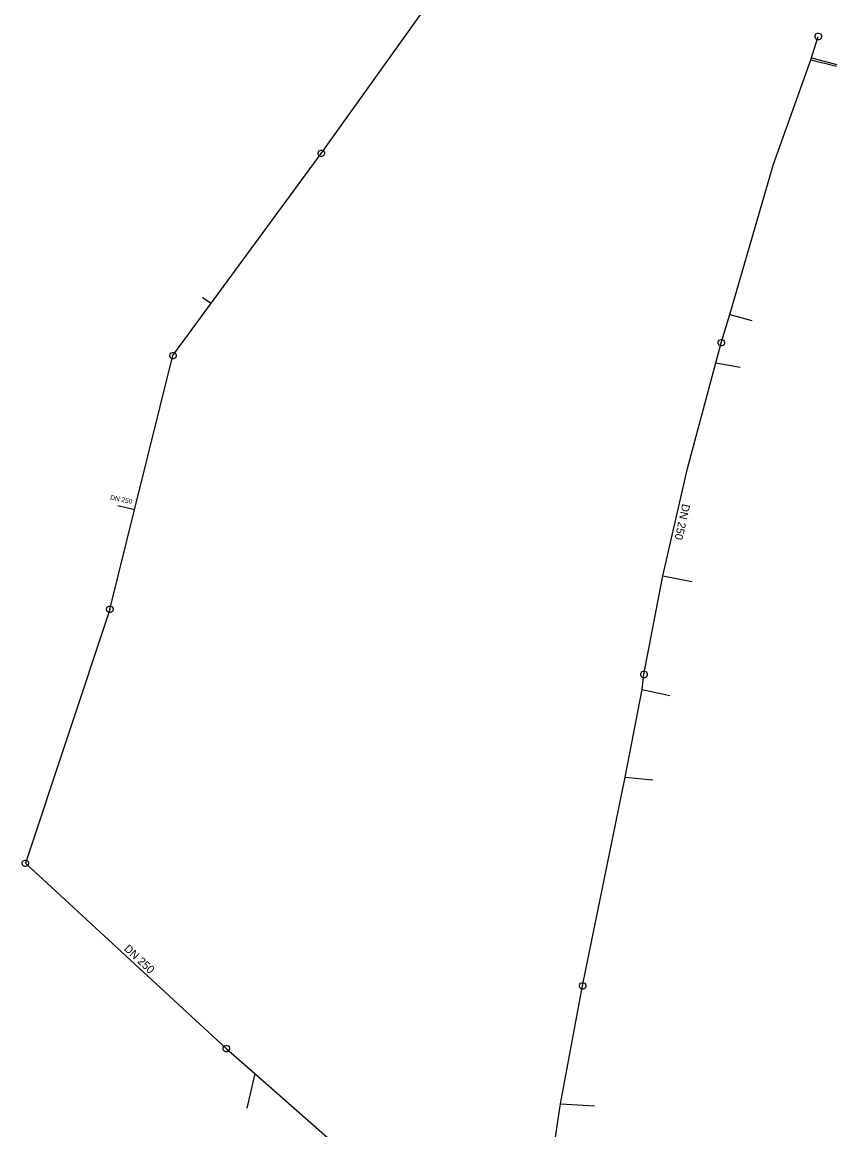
# Model space of a CAD drawing. Extents: x -717256 to -716843, y -1145423 to -1142840.
# Drawn here: x -717229.7 to -717102.4, y -1144225.5 to -1144052.4 of the extents above; entities that cross this region are included whole.
import ezdxf

# ---------------------------------------------------------------- set-up
doc = ezdxf.new("R2010")
doc.units = 0
doc.layers.add('Vrstva 30', color=7, linetype='Continuous')
doc.layers.add('Vrstva 31', color=7, linetype='Continuous')

msp = doc.modelspace()

# ---------------------------------------------------------------- linework, layer by layer
at = {"layer": 'Vrstva 30'}
for p, q in [((-717182.99, -1144072.917), (-717155.294, -1144034.126)), ((-717106.494, -1144058.295), (-717105.338, -1144054.658)), ((-717105.838, -1144054.558), (-717105.788, -1144054.408)), ((-717105.838, -1144054.758), (-717105.838, -1144054.558)), ((-717105.738, -1144055.008), (-717105.838, -1144054.758)), ((-717105.788, -1144054.408), (-717105.688, -1144054.258)), ((-717105.588, -1144055.108), (-717105.738, -1144055.008)), ((-717105.688, -1144054.258), (-717105.438, -1144054.158)), ((-717105.438, -1144055.158), (-717105.588, -1144055.108)), ((-717105.438, -1144054.158), (-717105.238, -1144054.158)), ((-717105.238, -1144055.158), (-717105.438, -1144055.158)), ((-717105.238, -1144054.158), (-717104.988, -1144054.258)), ((-717105.088, -1144055.108), (-717105.238, -1144055.158)), ((-717104.938, -1144055.008), (-717105.088, -1144055.108)), ((-717104.988, -1144054.258), (-717104.888, -1144054.408)), ((-717104.838, -1144054.758), (-717104.938, -1144055.008)), ((-717104.888, -1144054.408), (-717104.838, -1144054.558)), ((-717104.838, -1144054.558), (-717104.838, -1144054.758)), ((-717112.339, -1144074.608), (-717106.494, -1144058.295)), ((-717183.49, -1144072.817), (-717183.44, -1144072.667)), ((-717183.49, -1144073.017), (-717183.49, -1144072.817)), ((-717183.44, -1144072.667), (-717183.34, -1144072.517)), ((-717183.34, -1144072.517), (-717183.09, -1144072.417)), ((-717183.09, -1144072.417), (-717182.89, -1144072.417)), ((-717182.89, -1144072.417), (-717182.64, -1144072.517)), ((-717182.64, -1144072.517), (-717182.54, -1144072.667)), ((-717182.54, -1144072.667), (-717182.49, -1144072.817)), ((-717182.49, -1144072.817), (-717182.49, -1144073.017)), ((-717206.171, -1144104.518), (-717182.99, -1144072.917)), ((-717183.39, -1144073.267), (-717183.49, -1144073.017)), ((-717183.24, -1144073.367), (-717183.39, -1144073.267)), ((-717183.09, -1144073.417), (-717183.24, -1144073.367)), ((-717182.89, -1144073.417), (-717183.09, -1144073.417)), ((-717182.74, -1144073.367), (-717182.89, -1144073.417)), ((-717182.59, -1144073.267), (-717182.74, -1144073.367)), ((-717182.49, -1144073.017), (-717182.59, -1144073.267)), ((-717119.132, -1144098.105), (-717112.339, -1144074.608)), ((-717120.483, -1144102.511), (-717119.132, -1144098.105)), ((-717120.983, -1144102.411), (-717120.933, -1144102.261)), ((-717120.933, -1144102.261), (-717120.833, -1144102.111)), ((-717120.833, -1144102.111), (-717120.583, -1144102.011)), ((-717120.583, -1144102.011), (-717120.383, -1144102.011)), ((-717120.383, -1144102.011), (-717120.133, -1144102.111)), ((-717120.133, -1144102.111), (-717120.033, -1144102.261)), ((-717120.033, -1144102.261), (-717119.983, -1144102.411)), ((-717121.339, -1144105.656), (-717120.483, -1144102.511)), ((-717120.983, -1144102.611), (-717120.983, -1144102.411)), ((-717120.883, -1144102.861), (-717120.983, -1144102.611)), ((-717120.733, -1144102.961), (-717120.883, -1144102.861)), ((-717120.583, -1144103.011), (-717120.733, -1144102.961)), ((-717120.383, -1144103.011), (-717120.583, -1144103.011)), ((-717120.233, -1144102.961), (-717120.383, -1144103.011)), ((-717120.083, -1144102.861), (-717120.233, -1144102.961)), ((-717119.983, -1144102.611), (-717120.083, -1144102.861)), ((-717119.983, -1144102.411), (-717119.983, -1144102.611)), ((-717212.205, -1144128.621), (-717206.171, -1144104.518)), ((-717206.671, -1144104.418), (-717206.621, -1144104.268)), ((-717206.671, -1144104.618), (-717206.671, -1144104.418)), ((-717206.571, -1144104.868), (-717206.671, -1144104.618)), ((-717206.621, -1144104.268), (-717206.521, -1144104.118)), ((-717206.421, -1144104.968), (-717206.571, -1144104.868)), ((-717206.521, -1144104.118), (-717206.271, -1144104.018)), ((-717206.271, -1144105.018), (-717206.421, -1144104.968)), ((-717206.271, -1144104.018), (-717206.071, -1144104.018)), ((-717206.071, -1144105.018), (-717206.271, -1144105.018)), ((-717206.071, -1144104.018), (-717205.821, -1144104.118)), ((-717205.921, -1144104.968), (-717206.071, -1144105.018)), ((-717205.771, -1144104.868), (-717205.921, -1144104.968)), ((-717205.821, -1144104.118), (-717205.721, -1144104.268)), ((-717205.671, -1144104.618), (-717205.771, -1144104.868)), ((-717205.721, -1144104.268), (-717205.671, -1144104.418)), ((-717205.671, -1144104.418), (-717205.671, -1144104.618)), ((-717125.783, -1144122.136), (-717121.339, -1144105.656)), ((-717129.64, -1144138.897), (-717125.783, -1144122.136)), ((-717212.205, -1144128.621), (-717214.808, -1144128.006)), ((-717216.038, -1144144.161), (-717212.205, -1144128.621)), ((-717132.574, -1144154.339), (-717129.64, -1144138.897)), ((-717216.488, -1144143.911), (-717216.388, -1144143.761)), ((-717216.388, -1144143.761), (-717216.138, -1144143.661)), ((-717216.138, -1144143.661), (-717215.938, -1144143.661)), ((-717215.938, -1144143.661), (-717215.688, -1144143.761)), ((-717215.688, -1144143.761), (-717215.588, -1144143.911)), ((-717216.038, -1144144.161), (-717229.244, -1144183.823)), ((-717216.538, -1144144.061), (-717216.488, -1144143.911)), ((-717216.538, -1144144.261), (-717216.538, -1144144.061)), ((-717216.438, -1144144.511), (-717216.538, -1144144.261)), ((-717216.288, -1144144.611), (-717216.438, -1144144.511)), ((-717216.138, -1144144.661), (-717216.288, -1144144.611)), ((-717215.938, -1144144.661), (-717216.138, -1144144.661)), ((-717215.788, -1144144.611), (-717215.938, -1144144.661)), ((-717215.638, -1144144.511), (-717215.788, -1144144.611)), ((-717215.538, -1144144.261), (-717215.638, -1144144.511)), ((-717215.588, -1144143.911), (-717215.538, -1144144.061)), ((-717215.538, -1144144.061), (-717215.538, -1144144.261)), ((-717133.074, -1144154.239), (-717133.024, -1144154.089)), ((-717133.024, -1144154.089), (-717132.924, -1144153.939)), ((-717132.924, -1144153.939), (-717132.674, -1144153.839)), ((-717132.674, -1144153.839), (-717132.474, -1144153.839)), ((-717132.474, -1144153.839), (-717132.224, -1144153.939)), ((-717132.224, -1144153.939), (-717132.124, -1144154.089)), ((-717132.124, -1144154.089), (-717132.074, -1144154.239)), ((-717133.074, -1144154.439), (-717133.074, -1144154.239)), ((-717132.974, -1144154.689), (-717133.074, -1144154.439)), ((-717132.824, -1144154.789), (-717132.974, -1144154.689)), ((-717132.874, -1144156.663), (-717132.574, -1144154.339)), ((-717132.674, -1144154.839), (-717132.824, -1144154.789)), ((-717132.474, -1144154.839), (-717132.674, -1144154.839)), ((-717132.324, -1144154.789), (-717132.474, -1144154.839)), ((-717132.174, -1144154.689), (-717132.324, -1144154.789)), ((-717132.074, -1144154.439), (-717132.174, -1144154.689)), ((-717132.074, -1144154.239), (-717132.074, -1144154.439)), ((-717135.507, -1144170.398), (-717132.874, -1144156.663)), ((-717142.162, -1144202.986), (-717135.507, -1144170.398)), ((-717229.744, -1144183.723), (-717229.694, -1144183.573)), ((-717229.694, -1144183.573), (-717229.594, -1144183.423)), ((-717229.594, -1144183.423), (-717229.344, -1144183.323)), ((-717229.344, -1144183.323), (-717229.144, -1144183.323)), ((-717229.144, -1144183.323), (-717228.894, -1144183.423)), ((-717228.894, -1144183.423), (-717228.794, -1144183.573)), ((-717228.794, -1144183.573), (-717228.744, -1144183.723)), ((-717229.744, -1144183.923), (-717229.744, -1144183.723)), ((-717229.644, -1144184.173), (-717229.744, -1144183.923)), ((-717229.494, -1144184.273), (-717229.644, -1144184.173)), ((-717229.344, -1144184.323), (-717229.494, -1144184.273)), ((-717229.144, -1144184.323), (-717229.344, -1144184.323)), ((-717197.839, -1144212.775), (-717229.244, -1144183.823)), ((-717228.994, -1144184.273), (-717229.144, -1144184.323)), ((-717228.844, -1144184.173), (-717228.994, -1144184.273)), ((-717228.744, -1144183.923), (-717228.844, -1144184.173)), ((-717228.744, -1144183.723), (-717228.744, -1144183.923)), ((-717142.612, -1144202.736), (-717142.512, -1144202.586)), ((-717142.512, -1144202.586), (-717142.262, -1144202.486)), ((-717142.262, -1144202.486), (-717142.062, -1144202.486)), ((-717142.062, -1144202.486), (-717141.812, -1144202.586)), ((-717141.812, -1144202.586), (-717141.712, -1144202.736)), ((-717145.608, -1144221.417), (-717142.162, -1144202.986)), ((-717142.662, -1144202.886), (-717142.612, -1144202.736)), ((-717142.662, -1144203.086), (-717142.662, -1144202.886)), ((-717142.562, -1144203.336), (-717142.662, -1144203.086)), ((-717142.412, -1144203.436), (-717142.562, -1144203.336)), ((-717142.262, -1144203.486), (-717142.412, -1144203.436)), ((-717142.062, -1144203.486), (-717142.262, -1144203.486)), ((-717141.912, -1144203.436), (-717142.062, -1144203.486)), ((-717141.762, -1144203.336), (-717141.912, -1144203.436)), ((-717141.662, -1144203.086), (-717141.762, -1144203.336)), ((-717141.712, -1144202.736), (-717141.662, -1144202.886)), ((-717141.662, -1144202.886), (-717141.662, -1144203.086)), ((-717198.339, -1144212.675), (-717198.289, -1144212.525)), ((-717198.339, -1144212.875), (-717198.339, -1144212.675)), ((-717198.239, -1144213.125), (-717198.339, -1144212.875)), ((-717198.289, -1144212.525), (-717198.189, -1144212.375)), ((-717198.189, -1144212.375), (-717197.939, -1144212.275)), ((-717197.939, -1144212.275), (-717197.739, -1144212.275)), ((-717197.839, -1144212.775), (-717193.377, -1144216.671)), ((-717197.739, -1144212.275), (-717197.489, -1144212.375)), ((-717197.489, -1144212.375), (-717197.389, -1144212.525)), ((-717197.339, -1144212.875), (-717197.439, -1144213.125)), ((-717197.389, -1144212.525), (-717197.339, -1144212.675)), ((-717197.339, -1144212.675), (-717197.339, -1144212.875)), ((-717198.089, -1144213.225), (-717198.239, -1144213.125)), ((-717197.939, -1144213.275), (-717198.089, -1144213.225)), ((-717197.739, -1144213.275), (-717197.939, -1144213.275)), ((-717197.589, -1144213.225), (-717197.739, -1144213.275)), ((-717197.439, -1144213.125), (-717197.589, -1144213.225)), ((-717193.377, -1144216.671), (-717167.355, -1144239.514)), ((-717148.036, -1144237.218), (-717145.608, -1144221.417))]:
    msp.add_line(p, q, dxfattribs=at)
at = {"layer": 'Vrstva 31'}
for p, q in [((-717106.494, -1144058.295), (-717102.469, -1144059.313)), ((-717106.393, -1144057.978), (-717102.428, -1144059.04)), ((-717200.186, -1144096.36), (-717201.566, -1144095.486)), ((-717119.132, -1144098.105), (-717115.735, -1144099.026)), ((-717121.339, -1144105.656), (-717117.553, -1144106.296)), ((-717129.64, -1144138.897), (-717125.087, -1144139.806)), ((-717132.874, -1144156.663), (-717128.542, -1144157.604)), ((-717135.507, -1144170.398), (-717131.207, -1144170.769)), ((-717193.377, -1144216.671), (-717194.619, -1144222.089)), ((-717145.608, -1144221.417), (-717140.32, -1144221.739))]:
    msp.add_line(p, q, dxfattribs=at)

# ---------------------------------------------------------------- texts
at = {"layer": 'Vrstva 30'}
for height, rotation, p in [(0.75, 348.3, (-717216.037, -1144126.99)), (1.25, 257.4, (-717126.56, -1144127.609)), (1.25, 316.8, (-717213.916, -1144197.308))]:
    msp.add_text('DN 250', height=height, rotation=rotation, dxfattribs=at).set_placement(p)

doc.saveas('drawing.dxf')
